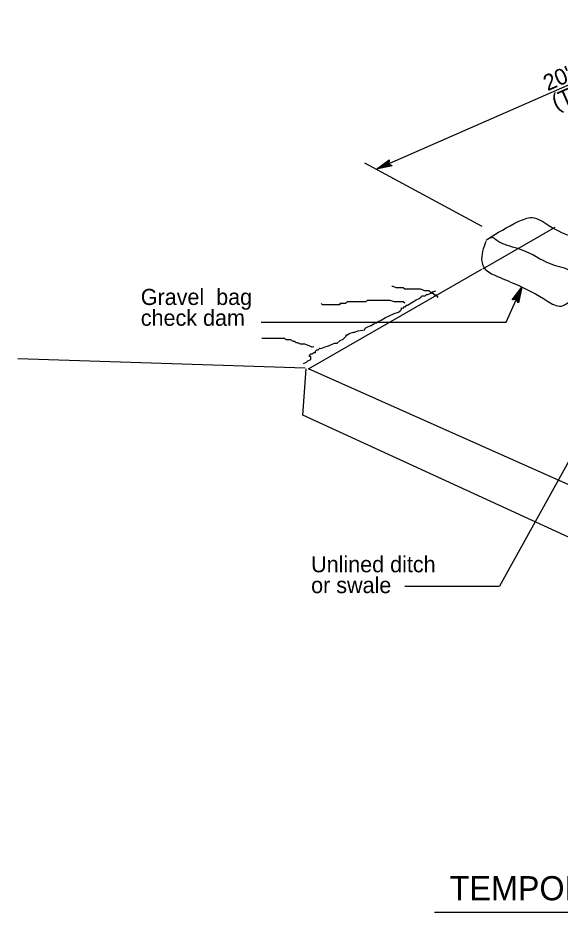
# Model space of a CAD drawing. Extents: x 6707415 to 6708768, y 1869893 to 1870831.
# Drawn here: x 6708162.2 to 6708364.3, y 1870028.6 to 1870362 of the extents above; entities that cross this region are included whole.
import ezdxf

# ---------------------------------------------------------------- set-up
doc = ezdxf.new("R2010")
doc.units = 0
for name, color, linetype in [('56 Stg 3 Anno', 7, 'Continuous'), ('57 Undefined', 7, 'Continuous'), ('60 Nongeo Data', 7, 'Continuous')]:
    doc.layers.add(name, color=color, linetype=linetype)

msp = doc.modelspace()

# ---------------------------------------------------------------- linework, layer by layer
at = {"layer": '56 Stg 3 Anno'}
for p, q in [((6708295.77, 1870305.59), (6708424.21, 1870362)), ((6708335.29, 1870284.22), (6708291.55, 1870307.88)), ((6708295.86, 1870305.63), (6708300.62, 1870309.12)), ((6708301.65, 1870306.78), (6708295.86, 1870305.63)), ((6708301.32, 1870307.01), (6708297.07, 1870306.17)), ((6708297.08, 1870306.17), (6708300.55, 1870308.72)), ((6708298.29, 1870306.7), (6708300.53, 1870308.34)), ((6708300.98, 1870307.23), (6708298.29, 1870306.7)), ((6708299.5, 1870307.23), (6708300.46, 1870307.94)), ((6708300.69, 1870307.47), (6708299.5, 1870307.23)), ((6708300.62, 1870309.12), (6708300.43, 1870307.64)), ((6708300.43, 1870307.64), (6708301.65, 1870306.78)), ((6708300.62, 1870309.12), (6708300.62, 1870309.12)), ((6708301.65, 1870306.78), (6708301.65, 1870306.78)), ((6708295.86, 1870305.63), (6708295.86, 1870305.63)), ((6708344.24, 1870248.56), (6708349.97, 1870261.57)), ((6708346.48, 1870256.82), (6708349.97, 1870261.57)), ((6708346.88, 1870256.87), (6708349.44, 1870260.36)), ((6708349.44, 1870260.35), (6708348.6, 1870256.13)), ((6708349.97, 1870261.57), (6708348.83, 1870255.79)), ((6708349.97, 1870261.57), (6708349.97, 1870261.57)), ((6708347.97, 1870257), (6708346.48, 1870256.82)), ((6708346.48, 1870256.82), (6708346.48, 1870256.82)), ((6708347.28, 1870256.94), (6708348.91, 1870259.15)), ((6708347.65, 1870256.96), (6708348.37, 1870257.93)), ((6708348.83, 1870255.79), (6708347.97, 1870257)), ((6708348.37, 1870257.93), (6708348.14, 1870256.77)), ((6708348.91, 1870259.15), (6708348.36, 1870256.42)), ((6708348.83, 1870255.79), (6708348.83, 1870255.79)), ((6708252.82, 1870248.56), (6708344.24, 1870248.56)), ((6708370.17, 1870201.4), (6708341.72, 1870150.18)), ((6708306.45, 1870150.14), (6708341.74, 1870150.14))]:
    msp.add_line(p, q, dxfattribs=at)
at = {"layer": '57 Undefined'}
msp.add_line((6708317.42, 1870028.6), (6708545.32, 1870028.6), dxfattribs=at)
at = {"layer": '60 Nongeo Data'}
for p, q in [((6708335.46, 1870268.47), (6708362.48, 1870284)), ((6708270.51, 1870231.15), (6708335.12, 1870268.28)), ((6708269.33, 1870231.46), (6708162.22, 1870234.91)), ((6708268.39, 1870213.92), (6708269.64, 1870231.15)), ((6708410.09, 1870168.95), (6708270.51, 1870231.15))]:
    msp.add_line(p, q, dxfattribs=at)
for points in [[(6708268.65, 1870233.12), (6708269.74, 1870233.62), (6708270.29, 1870234.13), (6708271.38, 1870234.63), (6708271.4, 1870235.17), (6708271.42, 1870235.7), (6708270.88, 1870235.72), (6708270.9, 1870236.25), (6708271.45, 1870236.77), (6708271.99, 1870236.75), (6708272.54, 1870237.27), (6708273.08, 1870237.25), (6708273.09, 1870237.79), (6708273.65, 1870238.3), (6708274.18, 1870238.28), (6708274.73, 1870238.8), (6708275.27, 1870238.78), (6708276.36, 1870239.28), (6708277.98, 1870239.76), (6708279.07, 1870240.26), (6708280.15, 1870240.76), (6708281.22, 1870240.73), (6708282.33, 1870241.76), (6708283.42, 1870242.26), (6708283.97, 1870242.77), (6708284.52, 1870243.29), (6708284.54, 1870243.83), (6708285.07, 1870243.81), (6708285.63, 1870244.32), (6708287.25, 1870244.81), (6708287.78, 1870244.79), (6708288.87, 1870245.29), (6708291.56, 1870245.73), (6708291.58, 1870246.27), (6708292.67, 1870246.77), (6708293.76, 1870247.26), (6708294.29, 1870247.25), (6708294.31, 1870247.78), (6708294.84, 1870247.76), (6708295.4, 1870248.28), (6708295.93, 1870248.26), (6708296.48, 1870248.78), (6708297.57, 1870249.28), (6708299.21, 1870250.29), (6708300.3, 1870250.79), (6708302.47, 1870251.79), (6708304.1, 1870252.27), (6708304.65, 1870252.79), (6708305.2, 1870253.3), (6708305.22, 1870253.84), (6708305.75, 1870253.82), (6708306.31, 1870254.34), (6708306.84, 1870254.32), (6708306.86, 1870254.85), (6708307.39, 1870254.84), (6708309.03, 1870255.85), (6708310.67, 1870256.87), (6708311.76, 1870257.37), (6708312.32, 1870257.88), (6708312.87, 1870258.4), (6708313.4, 1870258.38), (6708313.94, 1870258.36), (6708314.49, 1870258.88), (6708315.03, 1870258.86), (6708316.11, 1870259.36), (6708316.67, 1870259.88), (6708317.93, 1870260.25)], [(6708318.8, 1870257.72), (6708318.16, 1870258.67), (6708317.62, 1870258.67), (6708317.09, 1870259.21), (6708316.55, 1870259.21), (6708316.01, 1870259.74), (6708315.48, 1870260.28), (6708314.94, 1870260.28), (6708313.87, 1870260.28), (6708312.27, 1870260.81), (6708311.2, 1870260.81), (6708310.66, 1870260.81), (6708310.13, 1870260.81), (6708309.59, 1870260.81), (6708308.52, 1870260.81), (6708307.99, 1870260.81), (6708306.92, 1870260.81), (6708306.38, 1870260.81), (6708305.84, 1870261.35), (6708305.31, 1870261.35), (6708304.77, 1870261.35), (6708304.24, 1870261.35), (6708303.17, 1870261.35), (6708303.17, 1870261.35), (6708302.1, 1870261.88), (6708301.56, 1870261.88)], [(6708306.41, 1870255.67), (6708305.77, 1870256.09), (6708305.23, 1870256.09), (6708304.16, 1870256.09), (6708302.56, 1870256.09), (6708300.95, 1870256.62), (6708299.88, 1870256.62), (6708299.34, 1870256.62), (6708297.74, 1870256.62), (6708297.2, 1870256.62), (6708296.13, 1870256.62), (6708295.6, 1870256.62), (6708295.06, 1870256.62), (6708294.53, 1870256.62), (6708292.92, 1870256.62), (6708292.39, 1870256.62), (6708291.85, 1870256.09), (6708291.32, 1870256.09), (6708290.78, 1870256.09), (6708290.25, 1870256.09), (6708289.71, 1870256.09), (6708288.64, 1870256.09), (6708288.1, 1870256.09), (6708287.57, 1870256.09), (6708287.03, 1870256.09), (6708285.96, 1870256.09), (6708284.89, 1870256.09), (6708284.36, 1870255.55), (6708283.82, 1870255.55), (6708282.75, 1870255.55), (6708282.22, 1870255.55), (6708282.22, 1870255.02), (6708281.68, 1870255.02), (6708281.15, 1870255.02), (6708280.61, 1870255.02), (6708280.08, 1870255.02), (6708279, 1870255.02), (6708278.47, 1870255.02), (6708277.93, 1870255.02), (6708276.86, 1870255.02), (6708275.79, 1870255.02), (6708275.79, 1870255.02), (6708275.26, 1870255.55)], [(6708272.5, 1870239.37), (6708271.86, 1870239.26), (6708270.79, 1870239.79), (6708269.19, 1870240.33), (6708267.58, 1870240.33), (6708266.51, 1870240.86), (6708265.97, 1870240.86), (6708265.44, 1870241.39), (6708264.9, 1870241.39), (6708263.83, 1870241.93), (6708263.3, 1870241.93), (6708262.23, 1870241.93), (6708261.69, 1870242.46), (6708261.16, 1870242.46), (6708260.09, 1870242.46), (6708259.02, 1870242.46), (6708258.48, 1870242.46), (6708257.41, 1870242.46), (6708256.87, 1870242.46), (6708255.8, 1870242.46), (6708255.27, 1870242.46), (6708254.2, 1870242.46), (6708253.17, 1870242.46)], [(6708399.28, 1870153.7), (6708268.39, 1870213.92)]]:
    msp.add_lwpolyline(points, dxfattribs=at)
for points in [[(6708337.24, 1870279.53), (6708348.66, 1870286.04), (6708353.85, 1870287.52), (6708360.14, 1870284.57), (6708370.14, 1870280.13), (6708382.81, 1870272.53), (6708382.5, 1870270.58)], [(6708336.62, 1870278.61), (6708335.13, 1870271.21), (6708335.88, 1870269), (6708339.95, 1870266.04), (6708347.73, 1870262.71), (6708359.58, 1870256.43), (6708364.76, 1870254.58), (6708367.35, 1870256.06), (6708369.21, 1870259.76), (6708369.95, 1870263.82), (6708368.84, 1870266.78), (6708362.17, 1870269.74), (6708351.43, 1870274.91), (6708343.65, 1870277.5), (6708340.69, 1870278.98), (6708338.84, 1870280.08), (6708337.73, 1870279.71), (6708336.62, 1870278.98)]]:
    msp.add_spline(points, degree=3, dxfattribs=at)

# ---------------------------------------------------------------- texts
at = {"layer": '57 Undefined'}
for s, p in [("20' Max", (6708359.66, 1870334.62)), ('(Typ)', (6708362.78, 1870327.51))]:
    msp.add_text(s, height=6, rotation=23.7096, dxfattribs=at).set_placement(p)
for s, height, p in [('Gravel  bag', 6, (6708208.03, 1870254.96)), ('check dam', 6, (6708208.03, 1870247.19)), ('Unlined ditch ', 6, (6708271.5, 1870155.3)), ('or swale', 6, (6708271.5, 1870147.53)), ('TEMPORARY CHECK DAM (TYPE 2)', 9, (6708323.14, 1870033.01))]:
    msp.add_text(s, height=height, dxfattribs=at).set_placement(p)

doc.saveas('drawing.dxf')
